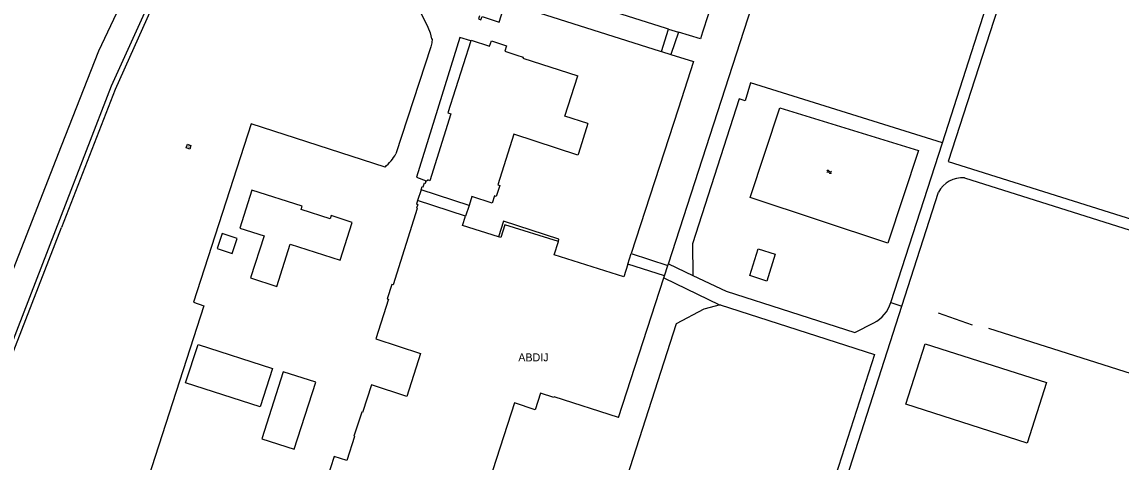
# Model space of a CAD drawing. Extents: x 135990 to 139000, y 393500 to 396000.
# Drawn here: x 136987.7 to 137331, y 394809.6 to 394947 of the extents above; entities that cross this region are included whole.
import ezdxf

# ---------------------------------------------------------------- set-up
doc = ezdxf.new("R2010")
doc.units = 0
for name, color, linetype in [('gg-afsc-muur', 7, 'Continuous'), ('gg-bbg-bijgebouw', 7, 'Continuous'), ('gg-bbg-bijgebouw onder overbouw', 7, 'Continuous'), ('gg-bbg-gedigitaliseerde bijgebouw', 7, 'Continuous'), ('gg-bbg-hoofdgebouw', 7, 'Continuous'), ('gg-bbg-onder overbouw', 7, 'Continuous'), ('gg-bbg-pand overbouw', 7, 'Continuous'), ('gg-knt-verharding', 7, 'Continuous'), ('gg-kntw-bovenkant insteek waterloop', 7, 'Continuous'), ('gg-kntw-midden sloot', 7, 'Continuous'), ('gt-anno-naam bijzondere bebouwing', 7, 'Continuous'), ('gt-grn-groengrens', 7, 'Continuous'), ('gt-grn-weggrens', 7, 'Continuous'), ('gt-symb-nortonput', 7, 'Continuous'), ('gt-symb-watersymbool', 7, 'Continuous')]:
    doc.layers.add(name, color=color, linetype=linetype)

# ---------------------------------------------------------------- blocks, each defined once
blk = doc.blocks.new('gt0-WA')
at = {"layer": 'gt-symb-watersymbool'}
for centre, start, end in [((-0.32, 0.02), 28.0725, 151.9275), ((0.43, 0.42), 208.0725, 331.9275), ((-0.32, -0.43), 28.0725, 151.9275), ((0.43, -0.03), 208.0725, 331.9275)]:
    blk.add_arc(centre, 0.425, start, end, dxfattribs=at)
blk = doc.blocks.new('gt0-NPUT')
at = {"layer": 'gt-symb-nortonput'}
blk.add_lwpolyline([(-0.57, -0.61), (-0.57, 0.59), (0.63, 0.59), (0.63, -0.61)], close=True, dxfattribs=at)
blk.add_text('N', height=0.7, dxfattribs=at).set_placement((-0.22, -0.38))

msp = doc.modelspace()

# ---------------------------------------------------------------- linework, layer by layer
at = {"layer": 'gg-afsc-muur'}
for points in [[(137036.95, 394971.187), (137016.77, 394925.98), (137000, 394882.844)], [(137001.036, 394723.915), (136945.61, 394742.94), (137000, 394882.844)]]:
    msp.add_lwpolyline(points, dxfattribs=at)
at = {"layer": 'gg-bbg-bijgebouw'}
for p, q in [((137127.943, 394941.127), (137128.02, 394941.37)), ((137134.33, 394941.11), (137139.03, 394939.61)), ((137164.5, 394915.369), (137161.533, 394905.957)), ((137174.08, 394823.46), (137188.219, 394867.169)), ((137188.219, 394867.169), (137188.4, 394867.73))]:
    msp.add_line(p, q, dxfattribs=at)
for points in [[(137127.943, 394941.127), (137120.76, 394918.619), (137121.65, 394918.35), (137115.14, 394897.47), (137114.42, 394897.69), (137114.31, 394897.34), (137113.96, 394897.46)], [(137128.02, 394941.37), (137133.775, 394939.49), (137134.33, 394941.11)], [(137139.03, 394939.61), (137138.489, 394937.949), (137142.325, 394936.696)], [(137142.325, 394936.696), (137144.24, 394936.07), (137144.14, 394935.77), (137161.29, 394930.259)], [(137161.533, 394905.957), (137161.37, 394905.44), (137141.38, 394911.981), (137136.34, 394896.199), (137136.93, 394895.97), (137135.85, 394892.579), (137135.27, 394892.779), (137134.58, 394890.489), (137128.26, 394892.52), (137127.36, 394889.749)], [(137112.36, 394894.59), (137112.7, 394895.64), (137113.05, 394895.53), (137113.43, 394896.75), (137113.71, 394896.66), (137113.96, 394897.46)], [(137059.527, 394894.475), (137055.751, 394882.685), (137063.317, 394880.262)], [(137071.464, 394877.652), (137087.06, 394872.657), (137090.835, 394884.447), (137084.287, 394886.576), (137083.969, 394885.582), (137074.899, 394888.481), (137075.213, 394889.462), (137059.527, 394894.475)], [(137111.29, 394891.251), (137110.95, 394890.18), (137111.3, 394890.069), (137110.91, 394888.848), (137111.17, 394888.76), (137103.64, 394864.969), (137103.24, 394865.079), (137101.79, 394860.589), (137102.23, 394860.43), (137098.2, 394848.03), (137112.228, 394843.478)], [(137136.536, 394879.947), (137125.3, 394883.46), (137126.27, 394886.419)], [(137155.25, 394878.45), (137138.52, 394883.729), (137137.23, 394879.73), (137136.536, 394879.947)], [(137054.918, 394879.461), (137050.18, 394880.997), (137048.644, 394876.271), (137053.386, 394874.734), (137054.918, 394879.461)], [(137177, 394871.448), (137175.681, 394867.397), (137153.899, 394874.305), (137155.25, 394878.45)], [(137217.7, 394876.199), (137222.96, 394874.529), (137220.37, 394866.138), (137215.12, 394867.808), (137217.7, 394876.199)], [(137038.79, 394834.346), (137042.674, 394846.34), (137065.921, 394838.824), (137062.034, 394826.819), (137038.79, 394834.346)], [(137301.695, 394815.48), (137263.794, 394827.635), (137269.865, 394846.554), (137307.763, 394834.4), (137301.695, 394815.48)], [(137112.228, 394843.478), (137107.89, 394830.098), (137096.826, 394833.671), (137094.041, 394825.11), (137093.821, 394825.177), (137091.393, 394817.647), (137091.595, 394817.582), (137089.179, 394810.089), (137085.162, 394811.297), (137081.736, 394800.676), (137103.269, 394793.695)], [(137062.606, 394816.841), (137072.72, 394813.595), (137079.431, 394834.502), (137069.316, 394837.748), (137062.606, 394816.841)], [(137174.08, 394823.46), (137153.893, 394829.972), (137153.828, 394829.769), (137149.646, 394831.118), (137147.958, 394825.917), (137141.506, 394828.035), (137100.55, 394701.319), (137075.841, 394709.32)]]:
    msp.add_lwpolyline(points, dxfattribs=at)
at = {"layer": 'gg-bbg-bijgebouw onder overbouw'}
for p, q in [((137127.36, 394889.749), (137112.36, 394894.59)), ((137126.27, 394886.419), (137111.29, 394891.251)), ((137188.4, 394867.73), (137177, 394871.448))]:
    msp.add_line(p, q, dxfattribs=at)
at = {"layer": 'gg-bbg-gedigitaliseerde bijgebouw'}
for points in [[(137164.5, 394915.369), (137157.311, 394917.635), (137161.29, 394930.259)], [(137063.317, 394880.262), (137059.09, 394867.086), (137067.248, 394864.468), (137071.464, 394877.652)]]:
    msp.add_lwpolyline(points, dxfattribs=at)
at = {"layer": 'gg-bbg-hoofdgebouw'}
for p, q in [((137206.403, 394962.697), (137200.304, 394943.862)), ((137189.699, 394944.844), (137188.741, 394945.143)), ((137187.111, 394937.944), (137187.441, 394937.84)), ((137192.665, 394919.812), (137178.05, 394874.69)), ((137189.44, 394870.97), (137189.622, 394871.532))]:
    msp.add_line(p, q, dxfattribs=at)
for points in [[(137189.622, 394871.532), (137220.35, 394966.49), (137211.811, 394969.148), (137216.29, 394982.72), (137215.16, 394983.169), (137220.549, 395000)], [(137188.741, 394945.143), (137173.17, 394950.001), (137176.55, 394961.81), (137179.79, 394960.828), (137183.98, 394973.99)], [(137130.583, 394948.941), (137130.27, 394948.04), (137131.06, 394947.759), (137131.41, 394948.751), (137136.74, 394946.939), (137138.71, 394953.189), (137187.111, 394937.944)], [(137200.304, 394943.862), (137199.62, 394941.749), (137192.739, 394943.895)], [(137190.4, 394936.908), (137197.48, 394934.678), (137192.665, 394919.812)]]:
    msp.add_lwpolyline(points, dxfattribs=at)
at = {"layer": 'gg-bbg-onder overbouw'}
for p, q in [((137187.441, 394937.84), (137189.699, 394944.844)), ((137192.739, 394943.895), (137190.4, 394936.908)), ((137178.05, 394874.69), (137189.44, 394870.97))]:
    msp.add_line(p, q, dxfattribs=at)
at = {"layer": 'gg-bbg-pand overbouw'}
for p, q in [((137189.699, 394944.844), (137192.739, 394943.895)), ((137187.441, 394937.84), (137190.4, 394936.908)), ((137112.36, 394894.59), (137111.29, 394891.251)), ((137127.36, 394889.749), (137126.27, 394886.419)), ((137177, 394871.448), (137178.05, 394874.69)), ((137188.4, 394867.73), (137189.44, 394870.97))]:
    msp.add_line(p, q, dxfattribs=at)
at = {"layer": 'gg-knt-verharding'}
for p, q in [((137275.232, 394909.345), (137292.652, 394963.384)), ((137259.128, 394859.389), (137275.232, 394909.345)), ((137262.526, 394858.292), (137273.98, 394893.93)), ((137189.622, 394871.532), (137197.305, 394867.872)), ((137242.151, 394794.9), (137262.526, 394858.292))]:
    msp.add_line(p, q, dxfattribs=at)
for points in [[(137104.84, 394964.853), (137114.46, 394945.42), (137115.17, 394943.61), (137115.63, 394941.73), (137115.8, 394941.74), (137115.69, 394940.58), (137115.42, 394939.26), (137104.51, 394905.86)], [(137297.28, 394965.96), (137277.09, 394903.44), (137411.04, 394861.251), (137412.565, 394860.822)], [(137127.943, 394941.127), (137124.49, 394942.21), (137110.93, 394898.57), (137113.96, 394897.46)], [(137282.12, 394898.35), (137413.38, 394856.91), (137427.16, 394850.809), (137447.131, 394837.837), (137623.771, 394745.397)], [(137155.25, 394878.45), (137155.36, 394879.19), (137138.06, 394884.84), (137136.536, 394879.947)], [(137188.219, 394867.169), (137205.65, 394858.699), (137205.783, 394858.656)], [(137197.305, 394867.872), (137207.66, 394862.94), (137247.901, 394850.03), (137253.801, 394853.089)], [(137205.783, 394858.656), (137200.725, 394857.364), (137192.026, 394852.756), (137172.753, 394792.852), (137154.45, 394778.462), (137137.508, 394765.576)], [(137205.783, 394858.656), (137253.98, 394843.231), (137240.888, 394802.319)]]:
    msp.add_lwpolyline(points, dxfattribs=at)
for centre, radius, start, end in [((137090.62, 394913.885), 16.041, 310.7906, 329.98233), ((137281.471, 394889.839), 8.536, 85.64219, 151.36151), ((137248.846, 394862.681), 10.796, 297.3194, 342.24785)]:
    msp.add_arc(centre, radius, start, end, dxfattribs=at)
at = {"layer": 'gg-kntw-bovenkant insteek waterloop'}
msp.add_line((136933.22, 394737.8), (137000, 394908.314), dxfattribs=at)
for points in [[(137000, 394886.685), (137015.63, 394927.08), (137035.809, 394971.697)], [(137000, 394908.314), (137011.63, 394938.01), (137019.218, 394954)], [(137215.159, 394892.207), (137224.415, 394920.263), (137267.74, 394906.901), (137258.206, 394878.004), (137215.159, 394892.207)], [(137000, 394722.875), (136944.09, 394742.19), (137000, 394886.685)]]:
    msp.add_lwpolyline(points, dxfattribs=at)
at = {"layer": 'gg-kntw-midden sloot'}
for p, q in [((137273.893, 394856.215), (137284.511, 394852.401)), ((137289.684, 394851.448), (137377.759, 394823.255))]:
    msp.add_line(p, q, dxfattribs=at)
at = {"layer": 'gt-grn-groengrens'}
for points in [[(137275.232, 394909.345), (137215.249, 394928.039), (137213.597, 394922.39), (137211.715, 394923.004), (137197.129, 394877.751), (137197.305, 394867.872)], [(137101.1, 394901.74), (137059.231, 394915.259), (137041.221, 394859.479), (137044.468, 394858.431), (137001.036, 394723.915)]]:
    msp.add_lwpolyline(points, dxfattribs=at)
at = {"layer": 'gt-grn-weggrens'}
msp.add_line((137259.128, 394859.389), (137262.526, 394858.292), dxfattribs=at)

# ---------------------------------------------------------------- block references
at = {"layer": 'gt-symb-nortonput', "rotation": 71.51067367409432}
msp.add_blockref('gt0-NPUT', (137039.693, 394908.042), dxfattribs=at)
at = {"layer": 'gt-symb-watersymbool'}
msp.add_blockref('gt0-WA', (137239.797, 394900.243), dxfattribs=at)

# ---------------------------------------------------------------- texts
at = {"layer": 'gt-anno-naam bijzondere bebouwing'}
msp.add_text('ABDIJ', height=2.5, rotation=0.34377, dxfattribs=at).set_placement((137142.738, 394841.005))

doc.saveas('drawing.dxf')
